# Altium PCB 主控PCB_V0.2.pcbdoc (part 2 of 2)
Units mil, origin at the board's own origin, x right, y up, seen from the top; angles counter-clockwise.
Board outline 2407.32 x 1620 mil, 2 copper layers (Top Layer, Bottom Layer); 44 components, 39 nets, 171 pads, 174 vias.
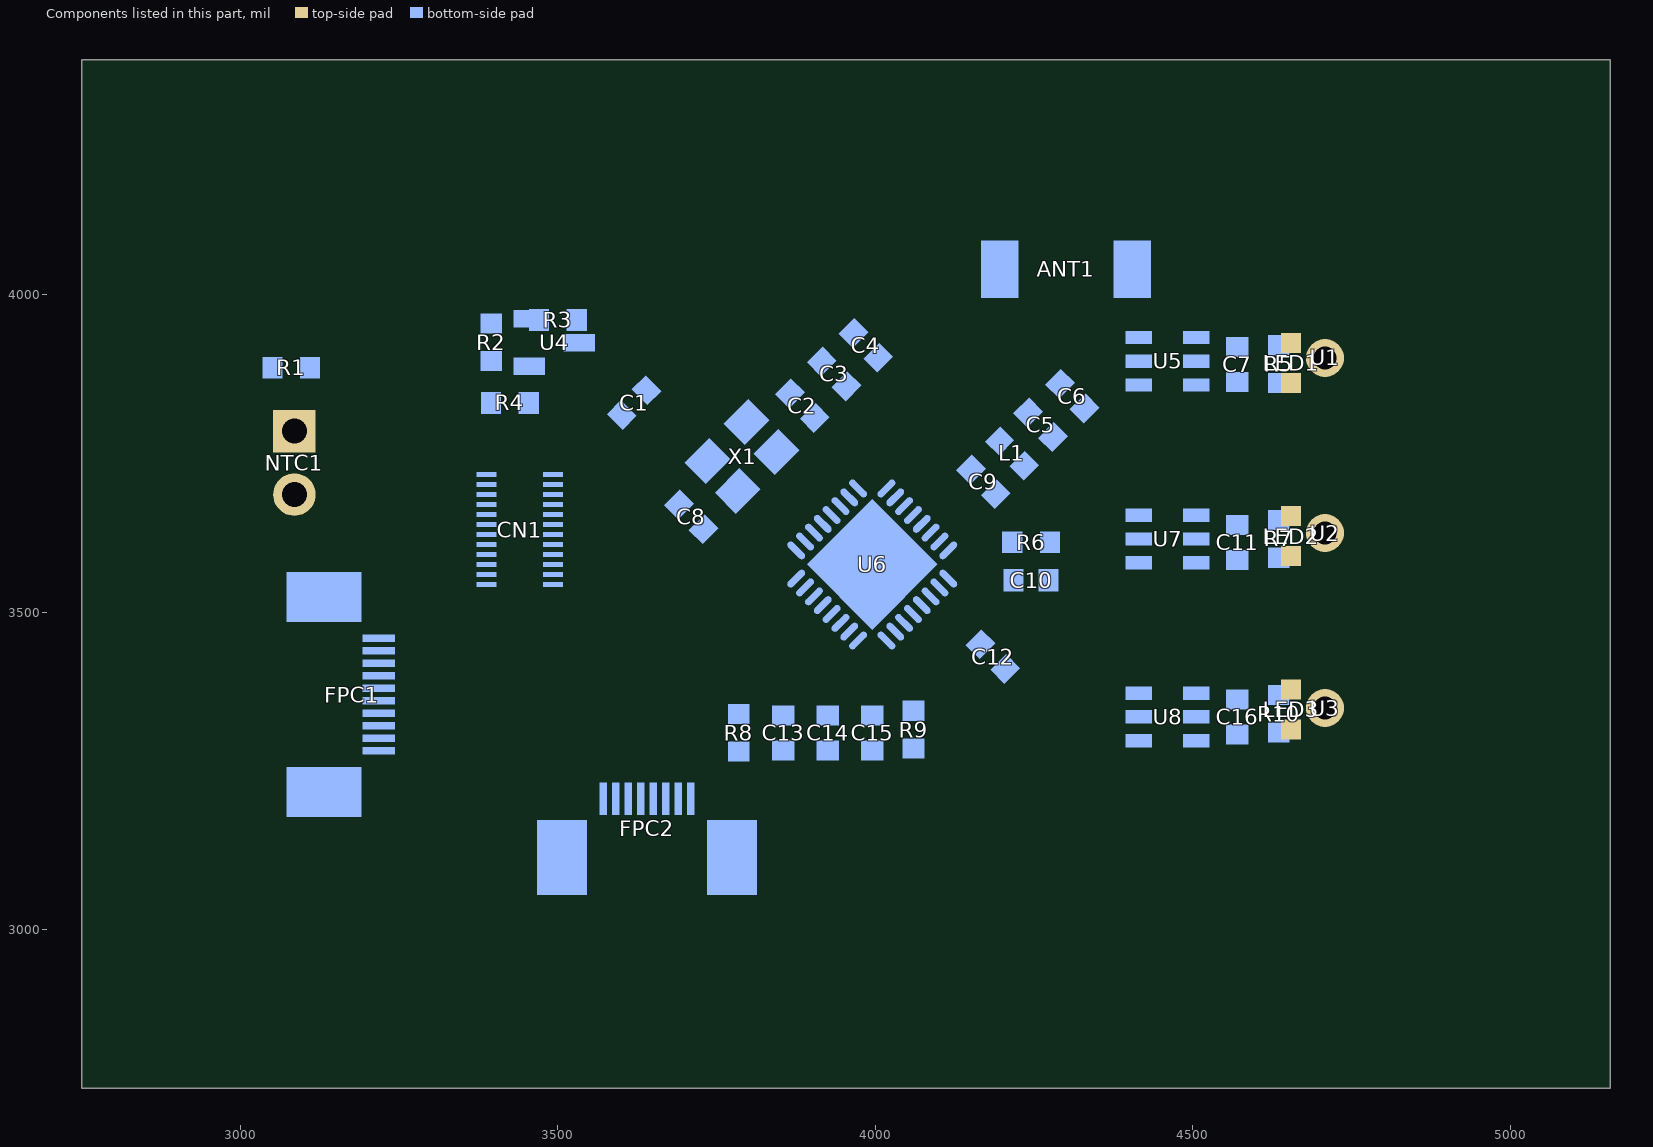
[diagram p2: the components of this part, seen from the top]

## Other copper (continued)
Bottom Layer:
  region net GND: 3204.4,3305 3160,3305 3159.4,3304.4 3159.4,3295.6 3204.4,3295.6
  region net GPIO3: 4149.86,3588.07 4156.93,3595.14 4157.79,3594.41 4158.76,3593.79 4160.98,3592.84 4163.35,3592.26 4165.67,3591.99 4153.01,3579.33 4152.74,3581.65 4152.16,3584.02 4151.21,3586.24 4150.59,3587.21
  region net GPIO9: 4510.24,3670.7 4500.24,3676.83 4500.1,3679.04 4499.73,3681.57 4499.21,3684.07 4498.61,3686.2 4515.04,3679.1 4514.03,3678.5 4513.11,3677.68 4512.29,3676.69 4511.59,3675.57 4511.02,3674.37 4510.6,3673.13 4510.33,3671.89
  region net GPIO4: 4516.25,3927.4 4519.83,3937.4 4522.03,3937.66 4524.18,3938.33 4526.26,3939.28 4528.24,3940.37 4524.66,3922.83 4523.03,3924.51 4520.89,3925.97 4518.53,3927.01 4517.36,3927.3
  region net GND: 4603.59,3955 4603.59,3965 4604.71,3965.09 4605.84,3965.34 4608.07,3966.23 4610.17,3967.5 4611.99,3968.95 4611.99,3951.05 4610.17,3952.5 4608.07,3953.77 4605.84,3954.66 4604.71,3954.91
  region net GND: 4639.46,3693.07 4646.53,3700.14 4647.39,3699.41 4648.36,3698.79 4650.58,3697.84 4652.95,3697.26 4655.27,3696.99 4642.61,3684.33 4642.34,3686.65 4641.76,3689.02 4640.81,3691.24 4640.19,3692.21
  region net GND: 4625.59,3420 4631.59,3430 4633.87,3430.12 4636.56,3430.45 4639.24,3430.92 4641.45,3431.47 4633.99,3415.2 4633.4,3416.23 4632.59,3417.17 4631.61,3417.99 4630.5,3418.68 4629.3,3419.24 4628.06,3419.66 4626.8,3419.91
  region net GPIO3: 3366.1,3721.61 3356.1,3726.07 3355.87,3728.25 3355.27,3730.4 3354.41,3732.48 3353.43,3734.48 3370.77,3730.02 3369.9,3729.32 3369.05,3728.44 3367.56,3726.28 3366.5,3723.89 3366.21,3722.71
  region net BL: 3448.99,3739.46 3458.99,3736.93 3459.27,3734.71 3460.02,3732.54 3461.07,3730.46 3462.28,3728.53 3444.56,3731.06 3446.18,3732.75 3447.6,3734.87 3448.61,3737.19 3448.89,3738.35
  region net 3V3: 3547.5,3463.62 3562.5,3463.62 3562.41,3461.23 3562.38,3459.09 3562.5,3458.09 3562.77,3457.12 3563.24,3456.16 3563.95,3455.21 3546.05,3455.21 3546.76,3456.16 3547.23,3457.12 3547.5,3458.09 3547.62,3459.09 3547.59,3461.23
  region net GPIO6: 4117.5,3448.91 4127.5,3448.91 4127.59,3447.79 4127.84,3446.66 4128.73,3444.43 4130,3442.33 4131.45,3440.51 4113.55,3440.51 4115,3442.33 4116.27,3444.43 4117.16,3446.66 4117.41,3447.79
  region net GPIO0: 3131.93,3909.86 3124.86,3916.93 3125.59,3917.79 3126.21,3918.76 3127.16,3920.98 3127.74,3923.35 3128.01,3925.67 3140.67,3913.01 3138.35,3912.74 3135.98,3912.16 3133.76,3911.21 3132.79,3910.59
  region net $1N3691: 3814.86,3223.07 3821.93,3230.14 3822.79,3229.41 3823.76,3228.79 3825.98,3227.84 3828.35,3227.26 3830.67,3226.99 3818.01,3214.33 3817.74,3216.65 3817.16,3219.02 3816.21,3221.24 3815.59,3222.21
  region net DN1: 3171.41,3365 3171.41,3355 3170.29,3354.91 3169.16,3354.66 3166.93,3353.77 3164.83,3352.5 3163.01,3351.05 3163.01,3368.95 3164.83,3367.5 3166.93,3366.23 3169.16,3365.34 3170.29,3365.09
  region net GPIO9: 4109.86,3338.07 4116.93,3345.14 4117.79,3344.41 4118.76,3343.79 4120.98,3342.84 4123.35,3342.26 4125.67,3341.99 4113.01,3329.33 4112.74,3331.65 4112.16,3334.02 4111.21,3336.24 4110.59,3337.21
  region net GPIO5: 4441.41,3495 4441.41,3485 4440.29,3484.91 4439.16,3484.66 4436.93,3483.77 4434.83,3482.5 4433.01,3481.05 4433.01,3498.95 4434.83,3497.5 4436.93,3496.23 4439.16,3495.34 4440.29,3495.09
  region net GPIO4: 4228.59,3507.99 4228.59,3517.99 4229.71,3518.08 4230.84,3518.33 4233.07,3519.23 4235.17,3520.49 4236.99,3521.94 4236.99,3504.04 4235.17,3505.49 4233.07,3506.76 4230.84,3507.65 4229.71,3507.9
  region net GND: 3757.74,3672.9 3771.88,3658.76 3770.07,3656.83 3768.46,3654.9 3765.85,3651.31 3764.06,3648.55 3763.11,3647.15 3746.13,3664.13 3747.52,3665.09 3750.29,3666.87 3753.87,3669.48 3755.8,3671.09
  region net GND: 3751.5,3638.38 3737.36,3652.52 3739.17,3654.46 3740.78,3656.39 3743.39,3659.97 3745.18,3662.74 3746.13,3664.13 3763.11,3647.15 3761.71,3646.2 3758.95,3644.41 3755.36,3641.8 3753.43,3640.19
  region net GND: 3640.86,3652.54 3660.86,3656.6 3660.75,3655.13 3660.47,3653.75 3659.89,3651.33 3659.82,3650.32 3660.04,3649.45 3660.67,3648.74 3661.83,3648.2 3646.55,3639.32 3646.74,3640.55 3646.75,3641.61 3646.6,3642.53 3646.31,3643.34 3645.43,3644.69 3644.29,3645.87 3643.07,3647.05 3641.97,3648.43 3641.52,3649.25 3641.17,3650.2 3640.95,3651.28
  region net GND: 3640.86,3703.11 3660.86,3703.11 3660.95,3700.47 3661.18,3697.96 3661.87,3693.58 3662.56,3690.36 3662.87,3688.7 3638.86,3688.7 3639.17,3690.36 3639.86,3693.58 3640.55,3697.96 3640.78,3700.47
  region net GND: 3660.86,3674.29 3640.86,3674.29 3640.78,3676.94 3640.55,3679.44 3639.86,3683.82 3639.17,3687.04 3638.86,3688.7 3662.87,3688.7 3662.56,3687.04 3661.87,3683.82 3661.18,3679.44 3660.95,3676.94
  region net GND: 3679.54,3766.18 3693.68,3752.04 3691.87,3750.11 3690.26,3748.18 3687.65,3744.59 3685.87,3741.83 3684.91,3740.43 3667.93,3757.41 3669.33,3758.37 3672.09,3760.15 3675.68,3762.76 3677.61,3764.37
  region net GND: 3673.3,3731.66 3659.16,3745.8 3660.97,3747.74 3662.58,3749.67 3665.19,3753.25 3666.98,3756.02 3667.93,3757.41 3684.91,3740.43 3683.52,3739.48 3680.75,3737.69 3677.17,3735.08 3675.24,3733.47
  region net GND: 3723.03,3781.39 3708.89,3795.53 3710.7,3797.47 3712.31,3799.4 3714.92,3802.98 3716.71,3805.75 3717.66,3807.14 3734.64,3790.16 3733.25,3789.21 3730.48,3787.42 3726.9,3784.81 3724.97,3783.2
  region net GND: 3729.27,3815.91 3743.41,3801.77 3741.6,3799.84 3739.99,3797.91 3737.38,3794.32 3735.6,3791.56 3734.64,3790.16 3717.66,3807.14 3719.06,3808.1 3721.82,3809.88 3725.41,3812.49 3727.34,3814.1
  region net GND: 3785.91,3860 3789.55,3840 3788.06,3840.12 3786.66,3840.4 3784.2,3840.99 3783.18,3841.07 3782.32,3840.84 3781.63,3840.2 3781.15,3839.03 3771.54,3853.86 3772.88,3853.71 3774.05,3853.74 3775.05,3853.94 3775.93,3854.26 3777.41,3855.22 3778.68,3856.44 3779.96,3857.71 3781.45,3858.86 3782.34,3859.32 3783.36,3859.68 3784.54,3859.92
  region net GND: 3766.4,3824.76 3752.26,3838.9 3754.07,3840.83 3755.68,3842.76 3758.29,3846.35 3760.08,3849.11 3761.03,3850.51 3778.01,3833.53 3776.61,3832.58 3773.85,3830.79 3770.26,3828.18 3768.33,3826.57
  region net GND: 3784.66,3833.95 3777.59,3826.88 3776.73,3827.61 3775.75,3828.23 3773.54,3829.18 3771.17,3829.76 3768.85,3830.03 3781.51,3842.69 3781.78,3840.37 3782.36,3838 3783.31,3835.78 3783.93,3834.81
  region net GND: 3806.14,3840 3806.14,3860 3808.78,3860.09 3811.29,3860.31 3815.67,3861 3818.89,3861.69 3820.55,3862.01 3820.55,3837.99 3818.89,3838.31 3815.67,3839 3811.29,3839.69 3808.78,3839.91
  region net GND: 3834.96,3860 3834.96,3840 3832.31,3839.91 3829.81,3839.69 3825.43,3839 3822.21,3838.31 3820.55,3837.99 3820.55,3862.01 3822.21,3861.69 3825.43,3861 3829.81,3860.31 3832.31,3860.09
  region net GND: 3888.8,3846.99 3888.8,3861.99 3891.19,3861.9 3893.33,3861.86 3894.33,3861.99 3895.3,3862.26 3896.26,3862.73 3897.2,3863.44 3897.2,3845.54 3896.26,3846.25 3895.3,3846.72 3894.33,3846.99 3893.33,3847.11 3891.19,3847.08
  region net GND: 4349.55,3904.39 4326.92,3910.04 4328.12,3911.05 4329.4,3911.91 4331.74,3913.34 4332.56,3914.04 4332.99,3914.79 4332.89,3915.66 4332.16,3916.69 4349.83,3917.05 4349.19,3916.18 4348.8,3915.33 4348.63,3914.5 4348.65,3913.7 4349.08,3912.14 4349.8,3910.62 4350.5,3909.11 4350.9,3907.59 4350.88,3906.81 4350.68,3906.02 4350.25,3905.22
  region net GND: 4355.24,3935 4355.24,3915 4352.59,3914.91 4350.09,3914.69 4345.71,3914 4342.49,3913.31 4340.83,3912.99 4340.83,3937.01 4342.49,3936.69 4345.71,3936 4350.09,3935.31 4352.59,3935.09
  region net GND: 4387.76,3935 4387.76,3915 4385.12,3914.91 4382.61,3914.69 4378.23,3914 4375.01,3913.31 4373.35,3912.99 4373.35,3937.01 4375.01,3936.69 4378.23,3936 4382.61,3935.31 4385.12,3935.09
  region net GND: 4358.95,3915 4358.95,3935 4361.59,3935.09 4364.1,3935.31 4368.48,3936 4371.69,3936.69 4373.35,3937.01 4373.35,3912.99 4371.69,3913.31 4368.48,3914 4364.1,3914.69 4361.59,3914.91
  region net GND: 4320.69,3875.52 4314.91,3898.03 4315.67,3898.66 4316.41,3899.05 4317.14,3899.23 4317.86,3899.23 4319.28,3898.86 4320.69,3898.2 4322.09,3897.56 4323.5,3897.19 4324.22,3897.19 4324.94,3897.38 4325.68,3897.77 4326.43,3898.41 4327.33,3880.76 4326.25,3881.42 4325.36,3881.47 4324.6,3881.04 4323.91,3880.24 4322.51,3877.95 4321.68,3876.7
  region net GND: 4326.97,3910.09 4349.48,3904.31 4348.3,3903.32 4347.05,3902.49 4344.76,3901.09 4343.96,3900.4 4343.53,3899.64 4343.58,3898.75 4344.24,3897.67 4326.59,3898.57 4327.23,3899.32 4327.62,3900.06 4327.81,3900.78 4327.81,3901.5 4327.44,3902.91 4326.8,3904.31 4326.14,3905.72 4325.77,3907.14 4325.77,3907.86 4325.95,3908.59 4326.34,3909.33
  region net GND: 4483.22,3958.49 4470.47,3974.03 4471.46,3974.71 4472.64,3975.12 4475.25,3975.53 4476.47,3975.75 4477.52,3976.11 4478.29,3976.73 4478.69,3977.7 4489.71,3963.89 4488.44,3963.85 4487.45,3963.54 4486.68,3963.02 4486.04,3962.32 4484.84,3960.53 4484.12,3959.52
  region net GND: 4492.39,3995.95 4507.65,3982.93 4505.72,3981.38 4504.03,3980.22 4503.36,3979.6 4502.86,3978.86 4502.58,3977.92 4502.54,3976.71 4488.72,3987.73 4489.7,3988.13 4490.31,3988.9 4490.68,3989.95 4490.89,3991.18 4491.31,3993.78 4491.71,3994.97
  region net GND: 4455.72,3959.28 4469.86,3945.14 4468.05,3943.2 4466.44,3941.27 4463.83,3937.69 4462.04,3934.92 4461.09,3933.53 4444.11,3950.51 4445.5,3951.46 4448.27,3953.25 4451.85,3955.86 4453.79,3957.47
  region net GND: 4467.39,3928.22 4453.24,3921.15 4451.7,3922.88 4450.67,3924.41 4449.43,3927.1 4448.85,3928.36 4448.07,3929.66 4446.91,3931.04 4445.19,3932.57 4462.5,3935.22 4461.93,3934.08 4461.89,3933.12 4462.28,3932.29 4463,3931.54 4465.09,3930.06 4466.26,3929.21
  region net GND: 4498.49,3973.76 4487.57,3991.13 4488.41,3991.86 4489.25,3992.4 4490.9,3992.98 4492.51,3993.11 4494.06,3993.06 4495.55,3993.05 4496.95,3993.34 4497.62,3993.67 4498.27,3994.17 4498.89,3994.87 4499.48,3995.79 4505.1,3979.04 4503.88,3979.4 4502.92,3979.31 4502.14,3978.84 4501.48,3978.08 4500.2,3976.02 4499.44,3974.87
  region net GND: 4468.06,3943.34 4453.06,3956.62 4454.71,3958.4 4455.86,3959.92 4457.34,3962.54 4458.77,3965.21 4459.86,3966.79 4461.41,3968.65 4479.23,3952.55 4477.57,3950.82 4476.16,3949.56 4473.75,3947.85 4471.28,3946.18 4469.81,3944.98
  region net GND: 4478.54,3982.1 4491.83,3967.1 4489.48,3964.65 4487.74,3962.61 4485.23,3959.26 4482.66,3955.97 4480.83,3954.02 4478.37,3951.69 4462.27,3969.51 4464.86,3971.73 4467.01,3973.36 4470.54,3975.66 4474.01,3978.04 4476.07,3979.76
  region net GND: 3135.06,3662.98 3142.14,3670.06 3142.99,3669.32 3143.97,3668.7 3146.18,3667.76 3148.55,3667.17 3150.87,3666.9 3138.21,3654.25 3137.95,3656.57 3137.36,3658.94 3136.42,3661.15 3135.79,3662.13
  region net GND: 3497.16,3730.33 3487.16,3727.11 3487.06,3728.22 3486.78,3729.38 3485.75,3731.73 3484.3,3733.86 3482.64,3735.51 3500.25,3738.74 3499.12,3736.78 3498.13,3734.7 3497.43,3732.54
  region net GND: 3364.01,3579.89 3357.83,3569.89 3355.72,3569.71 3353.56,3569.25 3351.43,3568.61 3349.43,3567.86 3355.6,3584.67 3356.24,3583.72 3357.08,3582.83 3358.09,3582.02 3359.22,3581.31 3361.65,3580.27 3362.86,3579.98
  region net GND: 3340,3595.44 3350,3595.44 3350.09,3594.32 3350.34,3593.18 3351.23,3590.95 3352.5,3588.86 3353.95,3587.03 3336.05,3587.03 3337.5,3588.86 3338.77,3590.95 3339.66,3593.18 3339.91,3594.32
  region net GND: 4620.43,3430 cw(c4620.43,3496.61) 4575.43,3447.5 4567.93,3425
  region net GND: 3492.16,3585.64 ccw(c3492.16,3539.29) 3470.2,3580.1 3465.2,3590.64 3470.2,3601.58 ccw(c3492.16,3639.18) 3492.16,3595.64
  region net GND: 3492.16,3564.14 cw(c3492.16,3592.48) 3469.94,3574.89 3459.94,3574.89 cw(c3429.94,3615.47) 3429.94,3565 3429.94,3555 cw(c3429.94,3504.77) 3459.94,3545.06 3469.94,3545.06 cw(c3492.16,3522.39) 3492.16,3554.14
  region net 3V3: 4354.65,3324.65 cw(c4334.65,3327.86) 4334.65,3307.6 4364.65,3297.6 4394.65,3307.6 cw(c4394.65,3327.86) 4374.65,3324.65
  region net 3V3: 4381.46,3618.54 4388.54,3611.46 ccw(c4473.15,3526.85) 4376.53,3597.44 4369.62,3609.52 ccw(c4342.3,3657.7)
  region net 3V3: 4402.04,3582.6 4405,3572.6 ccw(c4405,3471.6) 4385,3570.6 4382.04,3584.15 ccw(c4402.04,3712.24)
  region net 3V3: 3532.54,3592.5 3540.25,3602.5 ccw(c3555.32,30628.81) 3555.25,3602.5 3547.5,3592.25 ccw(c3532.54,3144.77)
  region net GND: 4503.17,3607.93 ccw(c4503.17,3580.35) 4477.5,3590.43 4470,3612.93
  region net GND: 4420,3700 ccw(c4420,3760.36) 4462.5,3717.5 4470,3692.58 4462.5,3672.5 ccw(c4420,3629.64) 4420,3690
  region net $1N1984: 4657.02,3639.94 4666.54,3649.94 4673.56,3650.16 4679.07,3650.73 4683.58,3651.53 4687.59,3652.44 4691.59,3653.32 4696.1,3654.05 4701.61,3654.5 4708.63,3654.56 4678.02,3622.02 4677.76,3623.82 4677.28,3625.58 4676.61,3627.28 4675.76,3628.92 4674.75,3630.48 4673.58,3631.96 4672.28,3633.34 4670.86,3634.62 4669.34,3635.79 4667.73,3636.83 4666.04,3637.74 4664.29,3638.5 4662.5,3639.12 4660.69,3639.57 4658.85,3639.84
  region net $1N1983: 4656.99,3364.66 4666.23,3374.66 4673.37,3374.88 4678.98,3375.45 4683.57,3376.23 4687.65,3377.11 4691.73,3377.96 4696.32,3378.63 4701.92,3379 4709.05,3378.95 4677.99,3346.8 4677.75,3348.62 4677.29,3350.39 4676.63,3352.09 4675.79,3353.73 4674.79,3355.29 4673.63,3356.77 4672.34,3358.14 4670.92,3359.41 4669.39,3360.57 4667.78,3361.6 4666.08,3362.5 4664.33,3363.25 4662.53,3363.85 4660.69,3364.3 4658.84,3364.57
  region net $1N1982: 4657.05,3915.22 4666.85,3925.22 4673.75,3925.44 4679.17,3926.02 4683.6,3926.83 4687.53,3927.76 4691.46,3928.68 4695.89,3929.47 4701.3,3930 4708.2,3930.16 4678.05,3897.25 4677.77,3899.04 4677.28,3900.78 4676.6,3902.47 4675.73,3904.1 4674.71,3905.67 4673.54,3907.15 4672.24,3908.54 4670.81,3909.83 4669.29,3911.01 4667.68,3912.06 4666,3912.98 4664.27,3913.76 4662.49,3914.38 4660.68,3914.84 4658.87,3915.12
  region net GND: 3155,3270.27 3165,3270.27 ccw(c3182.65,3270.27) 3172.5,3255.82 3147.5,3255.82 ccw(c3137.35,3270.27)
  region net 3V3: 3177.59,3436.7 3177.59,3446.7 ccw(c3192.59,3505.12) 3192.59,3444.8 3192.59,3432.99 ccw(c3177.59,3404.48)
  region net DN1: 3177.59,3355 3177.59,3365 ccw(c3177.59,3471.61) 3192.59,3366.06 3192.59,3354.25 ccw(c3177.59,3204.72)
  region net GND: 3188.04,3293.3 3188.04,3303.3 ccw(c3188.04,3307.95) 3192.59,3307.01 3192.59,3295.2 ccw(c3192.59,3288.79)
  region net ADC_VIN: 3878.02,3321.61 3868.98,3316.51 ccw(c3853.07,3295.3) 3853.07,3321.81 3872.72,3337.52 ccw(c3899.23,3337.52)
  region net ADC_VIN: 3831.98,3355.95 3843.46,3358.61 ccw(c3859.37,3379.82) 3859.37,3353.31 3837.28,3340.04 ccw(c3810.77,3340.04)
  region net GND: 3761.69,3648.57 3747.55,3662.71 ccw(c3735.16,3675.1) 3749.2,3685.58 3780.25,3654.52 ccw(c3776.75,3633.51)
  region net GND: 3773.76,3830.71 3780.83,3837.78 ccw(c3794.09,3851.04) 3796.74,3832.47 3779.06,3814.8 ccw(c3760.5,3817.45)
  region net $1N1185: 3882.87,3735.92 3875.8,3728.85 ccw(c3862.54,3715.59) 3859.89,3734.15 3877.57,3751.83 ccw(c3896.13,3749.18)
  region net $1N1185: 3874.17,3782.27 3881.24,3775.2 ccw(c3894.5,3761.94) 3875.94,3759.29 3858.26,3776.96 ccw(c3860.91,3795.52)
  region net $1N1184: 3771.46,3753.54 3778.54,3746.46 ccw(c3810.16,3702.57) 3771.9,3740.82 3760.02,3752.7 ccw(c3765.26,3759.74)
  region net $1N1184: 3720.83,3692.73 3713.76,3699.8 ccw(c3700.5,3713.06) 3719.06,3715.71 3732.93,3701.85 ccw(c3759.27,3654.29)
  region net GND: 4373.35,3915 4373.35,3935 ccw(c4373.35,3965.12) 4393.66,3942.87 4393.66,3921.93 ccw(c4393.66,3888.71)
  region net GND: 4442.98,3939.9 4442.98,3924.9 ccw(c4442.98,3914.89) 4435.86,3921.93 4435.86,3942.87 ccw(c4442.98,3949.91)
  region net 3V3: 4445.2,3862.6 4445.2,3852.6 ccw(c4445.2,3841.9) 4435.86,3847.13 4435.86,3868.07 ccw(c4445.2,3873.3)
  region net 3V3: 4403.47,3839.24 4384.83,3834.74 ccw(c4352.33,3867.24) 4393.66,3847.13 4416.79,3847.13 ccw(c4425.55,3817.16)
  region net $1N1977: 4541.34,3865.9 4541.34,3855.9 ccw(c4541.34,3837.15) 4526.34,3848.4 4526.34,3868.07 ccw(c4541.34,3918.71)
  region net GND: 4471.09,3903.3 4482.18,3913.43 ccw(c4506.04,3945.25) 4506.04,3905.47 4484.14,3884.53 ccw(c4425.47,3857.68)
  region net GND: 4541.34,3900 4541.34,3890 ccw(c4541.34,3866.71) 4526.34,3884.53 4526.34,3905.47 ccw(c4541.34,3923.29)
  region net GPIO4: 4531.89,3937.4 4531.89,3927.4 ccw(c4531.89,3921.85) 4526.34,3921.93 4526.34,3942.87 ccw(c4531.89,3942.95)
  region net GND: 4409.76,3677.87 4419.76,3677.87 ccw(c4438.51,3677.87) 4427.26,3662.87 4402.26,3662.87 ccw(c4391.01,3677.87)
  region net 3V3: 4385,3610 4385,3620 ccw(c4385,3629.58) 4393.66,3625.47 4393.66,3604.53 ccw(c4385,3600.42)
  region net 3V3: 4378.66,3572.6 4378.66,3582.6 ccw(c4378.66,3605.89) 4393.66,3588.07 4393.66,3567.13 ccw(c4378.66,3549.31)
  region net $1N1981: 4541.34,3582.6 4541.34,3572.6 ccw(c4541.34,3549.31) 4526.34,3567.13 4526.34,3588.07 ccw(c4541.34,3605.89)
  region net GND: 4541.34,3620 4541.34,3610 ccw(c4541.34,3586.71) 4526.34,3604.53 4526.34,3625.47 ccw(c4541.34,3643.29)
  region net GND: 4477.07,3607.93 4477.07,3617.93 ccw(c4476.62,3625.43) 4484.14,3625.43 4484.14,3604.53 ccw(c4477.07,3598.89)
  region net GPIO9: 4500.24,3677.87 4510.24,3677.87 ccw(c4528.99,3677.87) 4517.74,3662.87 4492.74,3662.87 ccw(c4481.49,3677.87)
  region net GND: 4445,3379.9 4445,3364.9 ccw(c4445,3349.37) 4435.86,3361.93 4435.86,3382.87 ccw(c4445,3395.43)
  region net 3V3: 4375,3325 4375,3345 ccw(c4375,3713.6) 4393.66,3345.47 4393.66,3324.53 ccw(c4375,2956.4)
  region net 3V3: 4364.65,3287.6 4364.65,3307.6 ccw(c4364.65,4198.45) 4393.66,3308.07 4393.66,3287.13 ccw(c4364.65,2396.75)
  region net $1N1980: 4541.34,3302.6 4541.34,3292.6 ccw(c4541.34,3269.31) 4526.34,3287.13 4526.34,3308.07 ccw(c4541.34,3325.89)
  region net GND: 4542.44,3342.5 4542.44,3327.5 ccw(c4542.44,3282.43) 4526.34,3324.53 4526.34,3345.47 ccw(c4542.44,3387.57)
  region net GND: 4482.4,3327.5 4482.4,3342.5 ccw(c4480.73,3345.47) 4484.14,3345.47 4484.14,3324.53 ccw(c4480.73,3324.53)
  region net GPIO5: 4500.24,3397.87 4510.24,3397.87 ccw(c4528.99,3397.87) 4517.74,3382.87 4492.74,3382.87 ccw(c4481.49,3397.87)
  region net K: 3540,3895.56 3530,3895.56 ccw(c3511.25,3895.56) 3522.5,3910.56 3547.5,3910.56 ccw(c3558.75,3895.56)
  region net 3V3: 3415.23,3949.66 3415.23,3959.66 ccw(c3415.23,3978.41) 3430.23,3967.16 3430.23,3947.96 ccw(c3415.23,3882.54)
  region net $1N1544: 3415.23,3890.34 3415.23,3900.34 ccw(c3415.23,4195.42) 3430.23,3900.72 3430.23,3882.84 ccw(c3415.23,3871.59)
  region net 3V3: 3953.54,3709.39 3960.61,3716.46 3963.41,3713.37 3965.59,3710.56 3967.99,3707.24 3960.2,3699.45 3959.44,3700.71 3958.16,3703.13 3956.23,3706.19 3954.99,3707.8
  region net 3V3: 3990.77,3444.32 3983.69,3437.25 3979.75,3441.09 3977.79,3442.72 3975.84,3443.98 3973.89,3444.74 3972.92,3444.9 3971.94,3444.88 3970.96,3444.67 3969.97,3444.26 3968.99,3443.63 3967.99,3442.76 3985.25,3460.02 3984.38,3459.03 3983.75,3458.04 3983.34,3457.06 3983.13,3456.07 3983.11,3455.1 3983.27,3454.12 3984.03,3452.17 3985.29,3450.22 3986.92,3448.26
  region net $1N1223: 4046.89,3703.54 4053.96,3696.46 4047.12,3689.27 4043.73,3685.52 4035.94,3693.31 4039.69,3696.7
  region net 3V3: 3427.01,3959.66 3427.01,3949.66 ccw(c3427.01,3930.91) 3412.01,3942.16 3412.01,3967.16 ccw(c3427.01,3978.41)
  region net 3V3: 3363.82,3931.75 3372.62,3954.69 ccw(c3351.94,3970.54) 3377.99,3970.54 3377.99,3938.78 ccw(c3381.37,3914.2)
  region net $1N1544: 3427.01,3900.34 3427.01,3890.34 ccw(c3427.01,3871.59) 3412.01,3882.84 3412.01,3907.84 ccw(c3427.01,3919.09)
  region net $1N1544: 3400,3864.46 3390,3864.46 ccw(c3371.25,3864.46) 3382.5,3879.46 3407.5,3879.46 ccw(c3418.75,3864.46)
  region net BL: 3458.99,3797.33 3448.99,3797.33 ccw(c3430.24,3797.33) 3441.49,3812.33 3466.49,3812.33 ccw(c3477.74,3797.33)
  region net $1N1544: 3390,3861.35 3400,3861.35 ccw(c3418.75,3861.35) 3407.5,3846.35 3382.5,3846.35 ccw(c3371.25,3861.35)
  region net GPIO9: 4050,3375.54 4060,3375.54 ccw(c4078.75,3375.54) 4067.5,3360.54 4042.99,3360.54 ccw(c4030.44,3375.54)
  region net GPIO9: 4092.01,3349.66 4092.01,3339.66 ccw(c4092.01,3320.91) 4077.01,3332.16 4077.01,3357.16 ccw(c4092.01,3368.41)
  region net 3V3: 4320.54,3634.14 4320.54,3614.14 ccw(c4320.54,3576.64) 4290.54,3599.14 4290.54,3627.01 ccw(c4290.54,3693.65)
  region net 3V3: 4264.66,3657.01 4284.66,3657.01 ccw(c4364.19,3657.01) 4290.54,3627.01 4258.78,3627.01 ccw(c4185.13,3657.01)
  region net CHIP_EN: 4220.34,3577.99 4210.34,3577.99 ccw(c4191.59,3577.99) 4202.84,3592.99 4227.84,3592.99 ccw(c4239.09,3577.99)
  region net CHIP_EN: 4184.46,3615 4184.46,3625 ccw(c4184.46,3682.03) 4199.46,3627.01 4199.46,3607.5 ccw(c4184.46,3596.25)
  region net GPIO0: 3114.66,3859.66 3104.66,3859.66 ccw(c3096.28,3859.66) 3097.16,3867.99 3122.16,3867.99 ccw(c3123.04,3859.66)
  region net GPIO0: 3117.83,3909.9 3135.41,3913.34 ccw(c3213.02,3835.74) 3125.54,3902.01 3104.51,3902.01 ccw(c3095.75,3931.98)
  region net 3V3: 3036.45,3864.04 3029.38,3871.11 ccw(c3007.71,3886.8) 3034.46,3886.8 3051.01,3867.99 ccw(c3051.01,3839.2)
  region net $1N1984: 4667.01,3649.94 4667.01,3639.94 ccw(c4667.01,3621.19) 4652.01,3632.44 4652.01,3657.44 ccw(c4667.01,3668.69)
  region net $1N1981: 4602.99,3572.6 4602.99,3582.6 ccw(c4602.99,3601.35) 4617.99,3590.1 4617.99,3569.74 ccw(c4602.99,3531.79)
  region net $1N1983: 4667.01,3374.66 4667.01,3364.66 ccw(c4667.01,3345.91) 4652.01,3357.16 4652.01,3382.16 ccw(c4667.01,3393.41)
  region net $1N1980: 4602.99,3302.44 4602.99,3312.44 ccw(c4602.99,3331.19) 4617.99,3319.94 4617.99,3294.94 ccw(c4602.99,3283.69)
  region net $1N1982: 4667.01,3925.22 4667.01,3915.22 ccw(c4667.01,3896.47) 4652.01,3907.72 4652.01,3932.72 ccw(c4667.01,3943.97)
  region net $1N1977: 4602.99,3855.9 4602.99,3865.9 ccw(c4602.99,3884.65) 4617.99,3873.4 4617.99,3848.4 ccw(c4602.99,3837.15)
  region net GND: 3120.12,3690 3120.12,3680 3118.8,3679.83 3117.65,3679.35 3116.64,3678.59 3115.75,3677.59 3114.96,3676.38 3114.25,3675 3113,3671.9 3111.84,3668.56 3110.61,3665.28 3109.15,3662.35 3108.29,3661.1 3107.31,3660.06 3107.31,3709.94 3108.29,3708.9 3109.15,3707.65 3110.61,3704.72 3111.84,3701.44 3113,3698.1 3114.25,3695 3114.96,3693.62 3115.75,3692.41 3116.64,3691.41 3117.65,3690.65 3118.8,3690.17
  region net GPIO0: 3080,3833.46 3090,3833.46 ccw(c3108.75,3833.46) 3097.5,3818.46 3072.5,3818.46 ccw(c3061.25,3833.46)
  region net $1N1223: 4172.88,3736.24 4162.28,3746.85 ccw(c4137.66,3771.47) 4172.35,3768.59 4194.62,3746.32 ccw(c4197.5,3711.63)
  region net 3V3: 4276.41,3707.74 4262.27,3693.6 ccw(c4228.37,3659.7) 4233.59,3707.35 4257.65,3731.41 ccw(c4369.4,3800.73)
  region net GND: 3487.16,3735.55 3497.16,3735.55 ccw(c3515.91,3735.55) 3504.66,3720.55 3479.66,3720.55 ccw(c3468.41,3735.55)
  region net GPIO0: 3593.54,3786.46 3586.46,3793.54 ccw(c3580.14,3797.81) 3585.54,3803.22 3601.9,3786.85 ccw(c3597.93,3782.07)
  region net $1N1980: 4602.72,3312.44 4602.72,3302.44 ccw(c4602.72,3283.69) 4587.72,3294.94 4587.72,3319.94 ccw(c4602.72,3331.19)
  region net $1N1980: 4537.28,3292.6 4537.28,3302.6 ccw(c4537.28,3321.35) 4552.28,3310.1 4552.28,3291.69 ccw(c4537.28,3168.25)
  region net GND: 4560.43,3400.81 4575.43,3400.81 ccw(c4603.55,3400.81) 4586.68,3378.31 4552.28,3378.31 ccw(c4525.28,3400.81)
  region net GND: 4556.9,3338.86 4544.33,3347.5 ccw(c4512.51,3371.36) 4552.28,3371.36 4580.77,3346.81 ccw(c4580.77,3307.04)
  region net GND: 4562.93,3948.31 4572.93,3948.31 ccw(c4591.68,3948.31) 4580.43,3933.31 4555.43,3933.31 ccw(c4544.18,3948.31)
  region net GND: 4556.02,3896.51 4546.98,3901.61 ccw(c4525.77,3917.52) 4552.28,3917.52 4571.93,3901.81 ccw(c4571.93,3875.3)
  region net $1N1977: 4537.28,3855.9 4537.28,3865.9 ccw(c4537.28,3884.65) 4552.28,3873.4 4552.28,3848.4 ccw(c4537.28,3837.15)
  region net $1N1977: 4602.72,3865.9 4602.72,3855.9 ccw(c4602.72,3837.15) 4587.72,3848.4 4587.72,3873.4 ccw(c4602.72,3884.65)
  region net VDD_SPI: 3920,3368.31 3930,3368.31 ccw(c3948.75,3368.31) 3937.5,3353.31 3912.5,3353.31 ccw(c3901.25,3368.31)
  region net 3V3: 3990,3368.31 4000,3368.31 ccw(c4018.75,3368.31) 4007.5,3353.31 3982.5,3353.31 ccw(c3971.25,3368.31)
  region net 3V3: 4170.51,3424.72 4160.51,3421.93 ccw(c4134.26,3418.18) 4153.01,3436.93 4178.01,3439.72 ccw(c4196.76,3420.97)
  region net CHIP_EN: 4210.34,3582.72 4220.34,3582.72 ccw(c4239.09,3582.72) 4227.84,3567.72 4202.84,3567.72 ccw(c4191.59,3582.72)
  region net $1N1184: 3710.11,3696.16 3717.18,3689.09 ccw(c3730.44,3675.83) 3711.88,3673.18 3694.2,3690.85 ccw(c3696.85,3709.42)
  region net GND: 3747.55,3662.71 3761.69,3648.57 ccw(c3783.26,3627) 3753.15,3631.9 3730.88,3654.18 ccw(c3725.98,3684.29)
  region net $1N1223: 4173.65,3758.22 4184.26,3747.62 ccw(c4208.88,3722.99) 4174.18,3725.88 4151.9,3748.15 ccw(c4149.04,3782.83)
  region net $1N1223: 4121.71,3716.99 4124.49,3731.99 ccw(c4118.87,3771.36) 4146.99,3743.24 4144.21,3705.74 ccw(c4116.08,3677.61)
  region net GND: 4266.15,3845.73 4276.75,3835.12 ccw(c4316.4,3795.47) 4264.18,3815.88 4242.28,3837.77 ccw(c4246.26,3865.62)
  region net GND: 4317.18,3900.3 4331.32,3886.16 ccw(c4388.71,3828.77) 4314.18,3860.88 4291.9,3883.15 ccw(c4259.79,3957.69)
  region net GND: 4267.38,3825.75 4256.77,3836.35 ccw(c4232.15,3860.97) 4266.85,3858.1 4289.12,3835.82 ccw(c4291.99,3801.13)
  region net 3V3: 4357.04,3825.51 4354.26,3815.51 ccw(c4358.01,3789.26) 4339.26,3808.01 4342.04,3833.01 ccw(c4360.79,3851.76)
  region net 3V3: 3976.59,3879.68 3983.66,3872.61 ccw(c3997.24,3859.03) 3978.15,3856.9 3960.68,3874.38 ccw(c3963.33,3892.94)
  region net $1N1981: 4602.72,3582.6 4602.72,3572.6 ccw(c4602.72,3550.6) 4587.72,3566.69 4587.72,3590.1 ccw(c4602.72,3601.35)
  region net $1N1981: 4537.28,3572.6 4537.28,3582.6 ccw(c4537.28,3601.35) 4552.28,3590.1 4552.28,3566.69 ccw(c4537.28,3550.6)
  region net GND: 4565,3668.31 4575,3668.31 ccw(c4593.75,3668.31) 4582.5,3653.31 4557.5,3653.31 ccw(c4546.25,3668.31)
  region net GND: 4556.02,3616.51 4546.98,3621.61 ccw(c4525.77,3637.52) 4552.28,3637.52 4571.93,3621.81 ccw(c4571.93,3595.3)
  region net $1N1185: 3884.89,3778.84 3877.82,3785.91 ccw(c3864.56,3799.17) 3883.12,3801.82 3900.8,3784.15 ccw(c3898.15,3765.58)
  region net GND: 3889.4,3861.99 3905.21,3846.99 ccw(c3905.21,3730.42) 3889.18,3845.88 3866.9,3868.15 ccw(c3889.4,3906.14)
  region net GND: 3829.95,3840 3836.9,3860 ccw(c3836.9,3919.28) 3866.9,3868.15 3859.95,3825 ccw(c3822.45,3787.5)
  region net 3V3: 3996.99,3926.53 4011.99,3929.32 ccw(c4051.36,3934.94) 4023.24,3906.82 3985.74,3904.03 ccw(c3957.61,3932.16)
  region net 3V3: 3984.89,3873.84 3977.82,3880.91 ccw(c3964.56,3894.17) 3983.12,3896.82 4000.8,3879.15 ccw(c3998.15,3860.58)
  region net $1N1219: 4166.31,3983.78 4155.21,3987.87 ccw(c4136.62,4011.65) 4166.14,4005.35 4195.02,3994.72 ccw(c4199.54,3939.73)
  region net GND: 3922.09,3848.01 3911.34,3837.56 3909.72,3839.31 3908.24,3840.85 3907.45,3841.47 3906.58,3841.98 3905.58,3842.33 3904.4,3842.51 3917.21,3855.02 3917.36,3853.84 3917.7,3852.83 3918.19,3851.95 3918.81,3851.15 3920.34,3849.64
  region net GND: 3928.16,3820.74 3938.76,3831.34 3940.39,3829.59 3941.88,3828.06 3942.67,3827.43 3943.55,3826.94 3944.56,3826.59 3945.73,3826.43 3933.07,3813.77 3932.91,3814.94 3932.56,3815.95 3932.07,3816.83 3931.44,3817.62 3929.91,3819.11

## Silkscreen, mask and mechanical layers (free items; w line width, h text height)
Mechanical Layer:
  circle w1: c4709.01,3200.19 r27.56
  circle w1: c3161.77,3999.4 r27.56
  lines w1: 3225,3475.04 3323.43,3475.04 3323.43,3790 3225,3790 3225,3475.04
Mech6:
  circle w7.87: c4709.01,3349.79 r7.87
  circle w7.87: c4709.01,3625.38 r7.87
  circle w7.87: c4709.01,3900.97 r7.87
  lines w0.2: 3335,3096.38 4476.73,3096.38 4476.73,4120 3335,4120 3335,3096.38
